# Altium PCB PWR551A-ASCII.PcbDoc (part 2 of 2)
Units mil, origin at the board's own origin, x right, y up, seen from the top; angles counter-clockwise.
Board outline 7100 x 3800 mil, 2 copper layers (Top Layer, Bottom Layer), stack 62 mil thick; 141 components, 57 nets, 323 pads, 168 vias.
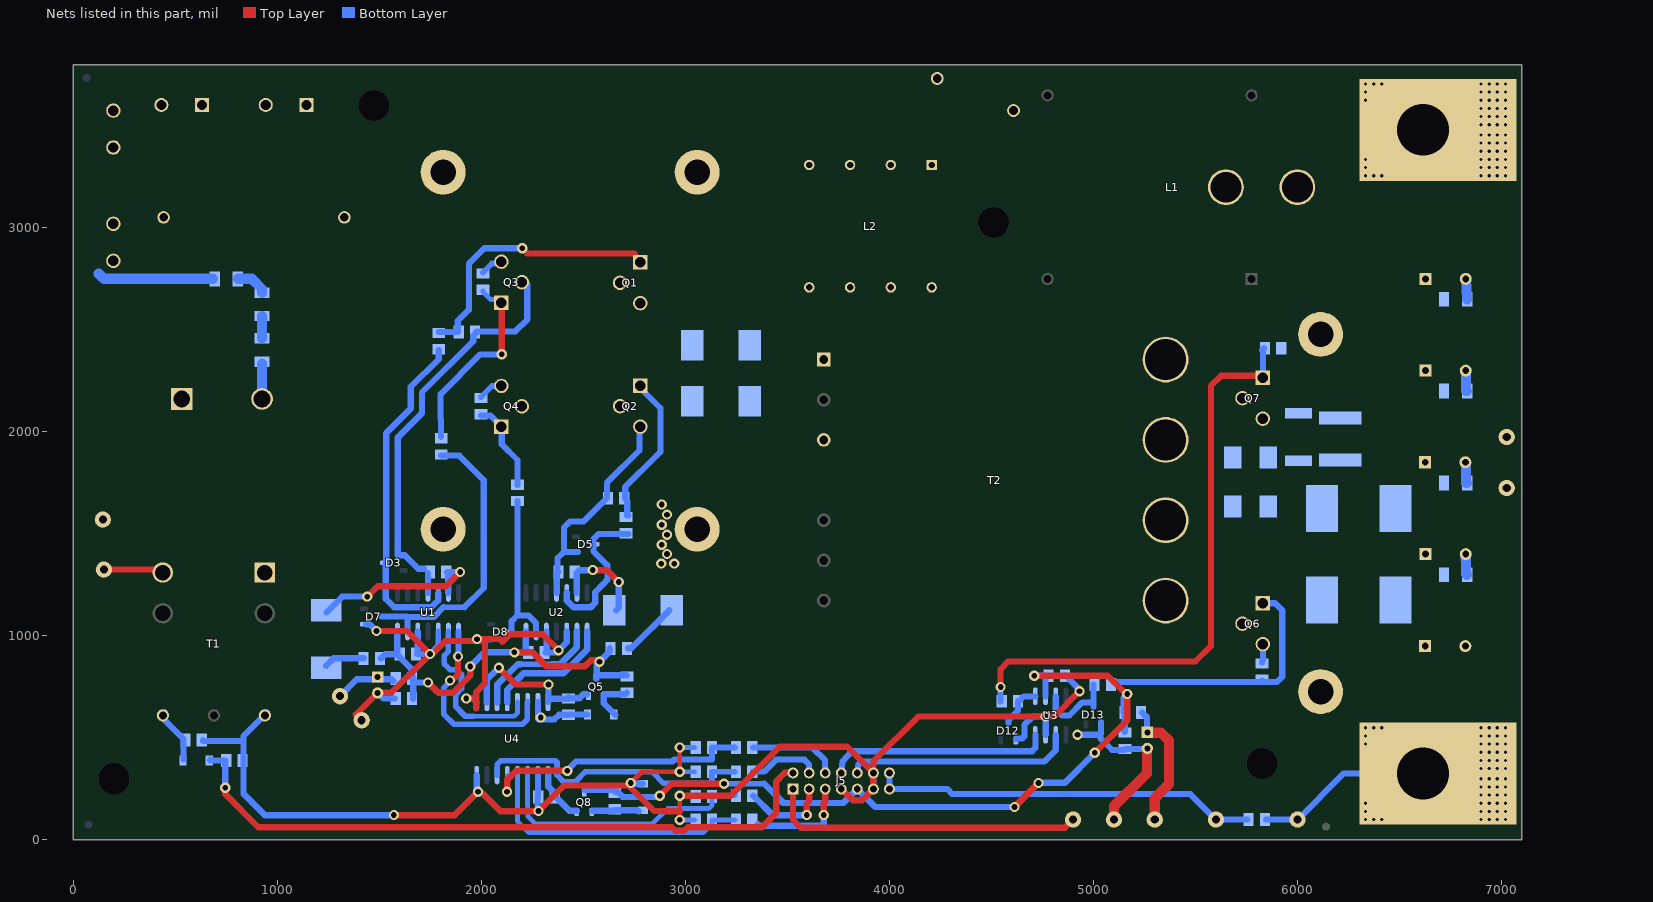
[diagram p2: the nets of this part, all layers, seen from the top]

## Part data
C1: "CAP, CERM, 0.22uF, 100V, +/-5%, C0G/NP0, 2220"
C2: "CAP, Film, 0.47uF, 275V, +/-20%, TH"
C3: "CAP, AL, 330uF, 450V, +/-20%, 0.553 ohm, TH"
C4 C5 C6 C7 C8: "CAP, AL, 1500uF, 16V, +/-20%, 0.031 ohm, TH"
C9 C10 C11 C12: library part C3216X7R1E105K/0.85, "CAP, CERM, 1 µF, 25 V, +/- 10%, X7R, 1206"
C13: "CAP, CERM, 1000pF, 400V, +/-20%, Y5U, Disc, 9.3x12.5mm"
C14 C15: "CAP, CERM, 0.1uF, 50V, +/-10%, X7R, 0805"
C16 C17 C18 C19 C20 C22 C23: "CAP, CERM, 1uF, 25V, +/-10%, X7R, 0805"
C21 C24: "CAP, AL, 22uF, 35V, +/-20%, TH"
D1: "Diode, Ultrafast, 100V, 0.15A, SOD-123"
D2 D9 D10 D11: "Diode, Ultrafast, 600 V, 3 A, SMC"
D3 D5 D7 D8 D12 D13: library part bat54-7-F, "Diode, Schottky, 30V, 0.2A, SOT-23"
D4 D6: "Diode, Superfast Rectifier, 100V, 3A, SMB"
D14 D15: "Diode, Zener, 5.6V, 500mW, SOD-123"
FC1 FC2: "Fuse Holder, 10A, TH"
FID1 FID2 FID3: "Fiducial mark.  There is nothing to buy or mount."
H1 H2 H3 H4: "Standoff, Hex, 0.5\"L #6-32 Nylon"
H5 H6 H7 H8: "HEX STANDOFF 6-32 NYLON 1-3/4\""
H27 H28 H29 H30 H31 H32: "MACHINE SCREW PAN PHILLIPS M3 5mm"
HS1 HS2 HS3: "HEATSINK VERT MAX CLIP, BLACK, 2 INCHES"
J1 J2: library part ED120/2DS, "TERMINAL BLOCK 5.08MM VERT 2POS, TH"
J3 J4: "Terminal 70A Lug"
J5: "Receptacle, 7x2, 2mm, TH"
L1: "Inductor, Shielded, ?, 2uH, A, 0.0009 ohm, TH"
L2: "Inductor, Shielded, ?, 26uH, A, 0.027 ohm, TH"
Logo1: library part TI_Logo, "Texas Instrument Corporate Signature"
LOGO2 LOGO5 LOGO8: library part IEC_HighVoltage, "IEC 61010-1 High Voltage Warning"
LOGO3 LOGO4 LOGO6 LOGO7: library part IEC_HotSurface, "IEC 61010-1 Hot Surface Warning"
Logo9: library part Pb-Free
Q1 Q2 Q3 Q4: "MOSFET, N-CH, 650V, 20.7A, TO-220AB"
Q5 Q8: library part "MMBT2222A, Fairchild Semiconductor", "Transistor, NPN, 40V, 0.15A, SOT-23"
Q6 Q7: "MOSFET, N-CH, 80V, 100A, TO-220AB"
R1: "RES, 48.7 ohm, 1%, 0.125W, 0805"
R2: "RES, 4.87k ohm, 1%, 0.125W, 0805"
R3 R12 R14: "RES, 1.0Meg ohm, 5%, 0.25W, 1206"
R4 R5 R13 R15: "RES, 3.01 ohm, 1%, 0.125W, 0805"
R6: "RES, 100 k, 1%, 1 W, 2512"
R7 R8: "RES, 1.00k ohm, 1%, 2W, 4527"
R9: "RES, 49.9, 1%, 0.125 W, 0805"
R10 R11 R16 R17 R24 R25: "RES, 10.0k ohm, 1%, 0.125W, 0805"
R18 R19: "RES, 2.20 ohm, 1%, 0.125W, 0805"
R20 R26 R27 R30 R32 R34: "RES, 7.15k ohm, 1%, 0.125W, 0805"
R21 R22: "RES, 6.19 ohm, 1%, 0.125W, 0805"
R23 R29: "RES, 5.11 ohm, 1%, 0.125W, 0805"
R28 R31 R33 R35: "RES, 5.11k ohm, 1%, 0.125W, 0805"
T1: "Transformer, 20 mH, TH"
T2: "Transformer, 2.75mH, TH"
TP1 TP4 TP8 TP10: library part 5000, "Test Point, Miniature, Red, TH"
TP2 TP3 TP7: library part 5002, "Test Point, Miniature, White, TH"
TP5 TP6 TP9 TP11: library part 5001, "Test Point, Miniature, Black, TH"
U1 U2: "High-Speed,4A, 600V High-side Low-side Gate Driver Device, D0014A"
U3: "Dual 5-A High-Speed Low-Side Gate Driver, D0008A"
U4: "150 Mbps Quad Channels, 4 / 0, Digital Isolator, 3.3 V / 5 V, -40 to +125 degC, 16-pin SOIC (DW), Green (RoHS & no Sb/Br)"
ZZ1 ZZ2 ZZ3 ZZ4: library part AssemblyNote

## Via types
v1: diameter 32, hole 16, Top Layer to Bottom Layer, 116 vias
v2: diameter 50, hole 28, Top Layer to Bottom Layer, tented both sides, 52 vias

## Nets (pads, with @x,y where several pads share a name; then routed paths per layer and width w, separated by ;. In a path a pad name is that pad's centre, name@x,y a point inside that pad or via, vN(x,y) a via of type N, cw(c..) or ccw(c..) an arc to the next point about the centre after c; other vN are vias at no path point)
CS: D1.1 J5.2 R1.1 | length 3309.7
  Top Layer w31.5: v2(745,255.91) 745,225 907.01,62.99 2933.28,62.99 2950.59,45.68 2994.29,45.68 3011.6,62.99 3375.71,62.99 3444.88,132.17 3444.88,286.44 3487.14,328.7 J5.2@3527.8,328.7
  Bottom Layer w30: D1.1@670,395 670,390 745,390 v2(745,255.91)
GND: C1.1 C4.2 C5.2 C6.2 C7.2 C8.2 C9.1 C10.1 C11.1 C12.1 C13.1 C18.1 C22.1 C23.1 C24.2 D12.1 D13.1 D15.2 HS3.1 HS3.2 J4.1 J5.7 J5.11 J5.12 Q6.3 Q7.3 R1.2 R2.2 R6.2 R24.2 R25.2 R28.1 R31.1 R33.1 R35.1 T1.3 TP5.1 TP11.1 U3.3 U4.2 U4.8 | length 8599.4
  Top Layer w23.62: v2@2720.47,267.72 v2(2732.28,279.53) 2787.4,334.65 v2(2972.48,334.65) 2972.48,452.71 v2(2972.44,452.76) ; 2832.68,155.51 2846.46,141.73 ; v2(2972.44,98.43) 2972.44,141.73 v2(2972.44,216.54)
  Top Layer w30: v2(2279.92,141.73) 2405.91,267.72 2720.47,267.72 2832.68,155.51 ; 2846.46,141.73 2890.16,141.73 ; J5.12@3921.3,328.7 3921.3,385.47 4140.83,605 v2(4765,605) 4807.76,605 v2(4931.1,728.35)
  Top Layer w31.5: v2(1571.26,122.05) 1869.29,122.05 v2(1983.46,236.22) ; v2@2004.33,230.32 2092.91,141.73 v2(2279.92,141.73) ; 2890.16,141.73 2972.44,141.73 ; v2(2972.44,216.54) 3222.09,216.54 3462.24,456.69 3793.31,456.69 3921.3,328.7 3921.3,250 3866.05,194.75 3819.72,194.75 3764.47,250 J5.7@3763.9,250
  Top Layer w50: TP11.1@5100,100 5100,165 5262.2,327.2 C24.2@5262.2,445.59
  Bottom Layer w23.62: v2@2972.44,106.3 2980.31,98.43 R31.1@3045.55,98.43 ; v2(2972.44,216.54) R28.1@3045.55,216.54 ; v2(2972.44,452.76) R33.1@3045.55,452.76 ; v2(2972.48,334.65) R35.1@3045.55,334.65
  Bottom Layer w30: R2.2@635,490 635,485 835,485 ; 835,225 835,485 ; T1.3@950,625 835,510 835,485 ; v2@2274.29,156.93 2274.29,210.63 2276.97,213.31 U4.2@2276.97,316.93 ; D12.1@4620.08,498.03 D12.1@4628.03,498.03 ; D12.1@4622.5,492.5 D12.1@4628.03,498.03 ; v2(4765,605) 4701.85,605 4661.42,564.57 4661.42,507.87 4651.57,498.03 D12.1@4628.03,498.03 ; C18.1@4865,805 4931.1,738.9 v2(4931.1,728.35) ; v2@4920.51,515 v2(4921.26,515.75) 5033.96,515.75 ; D13.1@5037.4,576.77 5037.4,519.19 5033.96,515.75 ; C24.2@5262.2,445.59 5158.31,445.59 5153.94,441.22 5090.67,441.22 5033.96,497.93 5033.96,515.75 ; R25.2@5825,870 5825,875 5830,880 Q6.3@5830,960
  Bottom Layer w31.5: 835,225 937.95,122.05 v2(1571.26,122.05) ; U4.8@1976.97,316.93 1976.97,242.72 v2(1983.46,236.22) ; v2@2738.09,275.1 D15.2@2791.73,275.1 ; J5.11@3920.73,250 3921.3,250 J5.12@3921.3,328.7 ; U3.3@4765,515 v2(4765,605)
  Bottom Layer w50: C6.2@6824,1850 6825,1850 6825,1750 C9.1@6830,1750 ; C5.2@6824,2300 6825,2300 6825,2200 C12.1@6830,2200 ; C4.2@6824,2750 6825,2750 C11.1@6830,2650 ; C10.1@6830,1300 6825,1305 C7.2@6825,1375 ; C7.2@6825,1375 6824,1376 6824,1400 6825,1400 C7.2@6825,1375
  other v1: 6332.91,3255.32 6372.91,3255.32 6412.91,3255.32 6899.17,3255.32 6939.17,3255.32 6979.17,3255.32 7019.17,3255.32 6332.91,3295.32 6899.17,3295.32 6939.17,3295.32 6979.17,3295.32 7019.17,3295.32 6332.91,3335.32 6899.17,3335.32 6939.17,3335.32 6979.17,3335.32 7019.17,3335.32 6899.17,3375.32 6939.17,3375.32 6979.17,3375.32 7019.17,3375.32 6899.17,3415.32 6939.17,3415.32 6979.17,3415.32 7019.17,3415.32 6899.17,3455.32 6939.17,3455.32 6979.17,3455.32 7019.17,3455.32 6899.17,3505.32 6939.17,3505.32 6979.17,3505.32 7019.17,3505.32 6899.17,3545.32 6939.17,3545.32 6979.17,3545.32 7019.17,3545.32 6899.17,3585.32 6939.17,3585.32 6979.17,3585.32 7019.17,3585.32 6332.91,3625.32 6899.17,3625.32 6939.17,3625.32 6979.17,3625.32 7019.17,3625.32 6332.91,3665.32 6899.17,3665.32 6939.17,3665.32 6979.17,3665.32 7019.17,3665.32 6332.91,3705.32 6372.91,3705.32 6412.91,3705.32 6899.17,3705.32 6939.17,3705.32 6979.17,3705.32 7019.17,3705.32
NetC1_2: C1.2 D4.1 D6.1 R6.1 R7.2 R8.2
NetC2_2: C2.2 C3.1 FC2.1 FC2.2 R3.2 T1.2 TP1.1 | length 870.4
  Top Layer w30: TP1.1@150,1325 T1.2@450,1325
  Bottom Layer w50: 125,2775 150,2750 R3.2@685.04,2750
NetC4_1: C4.1 C5.1 C6.1 C7.1 C8.1 C9.2 C10.2 C11.2 C12.2 J3.1 L1.14 R7.1 R8.1 R9.2 TP3.1 TP4.1 | length 898.2
  Bottom Layer w30: R9.2@5845,100 TP3.1@6000,100 6225,325 J3.1@6650,325
  other v1: 6332.91,100 6372.91,100 6412.91,100 6899.17,100 6939.17,100 6979.17,100 7019.17,100 6332.91,140 6899.17,140 6939.17,140 6979.17,140 7019.17,140 6332.91,180 6899.17,180 6939.17,180 6979.17,180 7019.17,180 6899.17,220 6939.17,220 6979.17,220 7019.17,220 6899.17,260 6939.17,260 6979.17,260 7019.17,260 6899.17,300 6939.17,300 6979.17,300 7019.17,300 6899.17,350 6939.17,350 6979.17,350 7019.17,350 6899.17,390 6939.17,390 6979.17,390 7019.17,390 6899.17,430 6939.17,430 6979.17,430 7019.17,430 6332.91,470 6899.17,470 6939.17,470 6979.17,470 7019.17,470 6332.91,510 6899.17,510 6939.17,510 6979.17,510 7019.17,510 6332.91,550 6372.91,550 6412.91,550 6899.17,550 6939.17,550 6979.17,550 7019.17,550
NetC14_1: C14.1 D3.1 L2.1 L2.2 L2.3 L2.4 Q1.3 Q3.2 R11.2 U1.11 | length 1982.9
  Bottom Layer w30: 1708.66,2090.55 1708.66,2192.91 1960,2444.25 1960,2471.81 1974.13,2485.94 1974.13,2490.16 1976.2,2492.22 2167.22,2492.22 2225,2550 2225,2725 Q3.2@2200,2725 ; U1.11@1738.58,1210.63 C14.1@1738.58,1308.78
  Bottom Layer w31.5: D3.1@1608.27,1395.67 1624.02,1395.67 1690.94,1328.74 1718.62,1328.74 ; D3.1@1608.27,1395.77 1590.55,1395.77 1590.55,1972.44 1708.66,2090.55
NetC14_2: C14.2 D10.1 U1.13 | length 916.8
  Top Layer w31.5: v2@1433.46,1185.04 v2(1440.94,1192.52) 1492.52,1244.09 1827.17,1244.09 v2(1896.06,1312.99)
  Bottom Layer w30: D10.1@1240.16,1114.25 1318.43,1192.52 v2(1440.94,1192.52)
  Bottom Layer w31.5: U1.13@1838.58,1210.63 1838.58,1307.2 1832.8,1312.99 v2(1896.06,1312.99)
NetC15_1: C15.1 D5.1 Q2.3 Q4.2 R10.1 T2.3 U2.11 | length 1092.1
  Bottom Layer w30: C15.1@2377.72,1312.99 2374.02,1316.69 2374.02,1381.89 2405.51,1413.39 ; D5.1@2474.41,1411.42 2407.48,1411.42 2405.51,1413.39 ; Q2.3@2775,2025 2775,1910 2615,1750 2615,1675 2500,1560 2434.02,1560 2405.51,1531.5 2405.51,1413.39
  Bottom Layer w31.5: U2.11@2368.5,1210.63 2368.5,1308.78 C15.1@2372.72,1312.99
NetC15_2: C15.2 D11.1 U2.13 | length 472.3
  Top Layer w31.5: v2(2545.67,1322.83) 2614.57,1322.83 2663.78,1273.62 v2@2663.78,1263.78
  Bottom Layer w31.5: U2.13@2468.5,1210.63 2468.5,1308.94 2472.56,1312.99 2482.4,1322.83 v2(2545.67,1322.83) ; D11.1@2661.73,1125.98 2673.62,1137.87 v2(2673.62,1263.78)
NetC19_2: C19.2 Q5.2 U4.10 U4.16 | length 739.2
  Top Layer w31.5: v2(2085.86,843.81) 2167.85,761.81 v2(2329.13,761.81)
  Bottom Layer w31.5: U4.10@2026.97,675.2 2026.97,784.92 v2(2085.86,843.81) ; U4.16@2329.13,678.27 v2(2329.13,761.81) ; 2342.05,691.18 2425.2,691.18 C19.2@2427.56,693.54 ; C19.2@2427.56,698.54 2432.56,693.54 2478.98,693.54 2500,714.57 Q5.2@2515.75,714.57
NetC21_1: C21.1 R23.2 TP8.1 | length 298.9
  Bottom Layer w31.5: TP8.1@1307.09,704.72 1389.76,787.4 1559.72,787.4 R23.2@1568.2,778.93
NetC22_2: C22.2 Q8.2 U4.1 | length 259.2
  Bottom Layer w31.5: U4.1@2326.97,316.93 2326.97,263.31 2359.29,230.99 C22.2@2359.29,215.63 ; C22.2@2359.29,210.63 C22.2@2359.29,215.63 ; Q8.2@2468.8,143.13 2431.79,143.13 C22.2@2359.29,215.63
NetC24_1: C24.1 R29.2 TP10.1 | length 648.3
  Top Layer w50: C24.1@5262.2,525.59 5331.1,525.59 5370.47,486.22 5370.47,275.47 5300,205 TP10.1@5300,100
  Bottom Layer w31.5: R29.2@5238.31,624.02 5262.2,600.12 C24.1@5262.2,525.59
NetD1_2: D1.2 R2.1 T1.5 | length 447.3
  Bottom Layer w30: T1.5@450,625 450,585 540,495 D1.2@540,395 ; D1.2@540,395 540,485 D1.2@540,395
NetD2_1: D2.1 Q1.2 Q2.2 T1.1
NetD2_2: D2.2 D9.1 L2.5 L2.6 L2.7 L2.8 T2.1
NetD3_3: D3.3 R4.1 U1.12 | length 1650.7
  Bottom Layer w30: D3.3@1533.46,1358.27 1531.5,1356.3 1531.5,1181.33 1572.51,1140.32 1754.66,1140.32 1788.58,1174.25 U1.12@1788.58,1210.63 ; 1655,2220.47 1791.34,2356.81 R4.1@1791.34,2399.88
  Bottom Layer w31.5: D3.3@1533.46,1358.27 1533.46,1994.09 1655,2115.63 1655,2220.47
NetD4_2: D4.2 Q7.2 T2.10
NetD5_3: D5.3 R5.1 U2.12 | length 745.9
  Bottom Layer w30: D5.3@2549.21,1448.82 2549.21,1415.75 2618.11,1346.85 2618.11,1274.61 2597.48,1253.98 ; D5.3@2550,1449.61 2550,1475.2 2574.8,1500 R5.1@2720,1500
  Bottom Layer w31.5: U2.12@2418.5,1210.63 2418.5,1173.19 2452.12,1139.57 2534.89,1139.57 2558.06,1162.75 2558.06,1214.57 2597.48,1253.98
NetD6_2: D6.2 Q6.2 T2.9
NetD7_3: D7.3 R15.1 U1.6 | length 1421.7
  Bottom Layer w27.56: 1814.06,1140.32 1917.32,1140.32
  Bottom Layer w30: D7.3@1509.84,1094.49 1631.89,1094.49 1634.42,1091.96 ; U1.6@1638.58,1021.65 1638.58,1087.8 1634.42,1091.96 ; R15.1@1803.15,1884.13 1891.46,1884.13 2011.81,1763.78 2011.81,1234.81 1917.32,1140.32 ; 1814.06,1140.32 1765.69,1091.96 1634.42,1091.96
NetD8_3: D8.3 R13.1 U2.6 | length 801
  Bottom Layer w30: D8.3@2148.43,1019.68 2148.43,1071.85 2177.17,1100.59 ; R13.1@2177.17,1660.79 2177.17,1100.59 ; U2.6@2268.5,1021.65 2268.5,1062.6 2230.51,1100.59 2177.17,1100.59
NetD10_2: D10.2 R18.2 | length 197.5
  Bottom Layer w31.5: D10.2@1240.16,854.25 1275.67,889.76 R18.2@1422.99,889.76
NetD11_2: D11.2 R19.2 | length 280.6
  Bottom Layer w31.5: R19.2@2718.62,938.98 2734.72,938.98 D11.2@2921.73,1125.98
NetD12_3: D12.3 R21.1 U3.5 | length 216.6
  Bottom Layer w30: D12.3@4582.68,572.83 4582.68,586.61 4629.91,633.84 R21.1@4629.91,679.9 ; R21.1@4635,680 4659,704 U3.5@4715,704
NetD13_3: D13.3 R22.1 U3.7 | length 392.5
  Bottom Layer w30: U3.7@4815,704 4815,640 4845,610 4881.89,610 4945.91,674.02 5000,674.02 D13.3@5000,651.57 ; D13.3@5000.67,679.65 R22.1@5000.67,761.81
NetD14_1: D14.1 Q5.1 R20.2 | length 239
  Bottom Layer w31.5: D14.1@2656.04,614.17 2600.39,669.82 2600.39,714.57 2705.75,714.57 R20.2@2712.99,721.81
NetD15_1: D15.1 Q8.1 R26.2 | length 232
  Bottom Layer w31.5: Q8.1@2543.8,143.13 2651.12,143.13 2653.94,145.94 2765.73,145.94 D15.1@2772.05,139.63
NetFC1_1: FC1.1 FC1.2 J1.1 J1.2
NetL1_13: L1.13 T2.7 T2.12
NetQ1_1: Q1.1 R4.2 R11.1 | length 1358.7
  Top Layer w30: v2(2200,2900) 2225,2875 2750,2875 Q1.1@2775,2825
  Bottom Layer w30: R4.2@1791.34,2489.88 1791.61,2490.16 1884.13,2490.16 1884.13,2543.58 1938.98,2598.43 1938.98,2824.8 2014.17,2900 v2(2200,2900)
NetQ2_1: Q2.1 R5.2 R10.2 | length 767.1
  Bottom Layer w30: R5.2@2720,1590 2715,1590 2715,1660 2705,1675 2705,1730 2859.25,1884.25 2860.63,1884.25 2877.95,1901.57 2877.95,2115.75 Q2.1@2767.72,2225.98 ; Q2.1@2770,2225 Q2.1@2775,2225
NetQ3_1: Q3.1 R15.2 R17.1 | length 927.1
  Top Layer w30: v2(2100,2380) Q3.1@2100,2625
  Bottom Layer w23.62: R17.1@2007.87,2691.22 2007.87,2687.01 2046.65,2648.23 Q3.1@2076.77,2648.23
  Bottom Layer w30: R15.2@1803.15,1974.13 1803.15,2061.85 1800,2065 1800,2185 1995,2380 v2(2100,2380)
NetQ4_1: Q4.1 R13.2 R16.1 | length 441.3
  Bottom Layer w30: R16.1@1998.03,2080.98 2044.02,2080.98 2100,2025 2100,1939.37 2177.17,1862.2 R13.2@2177.17,1740.79
NetQ6_1: Q6.1 R22.2 R25.1 | length 1274.9
  Bottom Layer w30: R22.2@5100,775 R25.1@5825,775 ; R25.1@5825,780 R25.1@5825,775 ; Q6.1@5830,1160 5890,1160 5925,1125 5925,800 5900,775 R25.1@5825,775
NetQ7_1: Q7.1 R21.2 R24.1 | length 2941.7
  Top Layer w30: v2(4545,750) 4545,836.62 4583.38,875 5500,875 5575,950 5575,2225 5625,2275 5825,2275 Q7.1@5830,2265
  Bottom Layer w30: R21.2@4545,680 v2(4545,750) ; Q7.1@5830,2265 5830,2395 5825,2400 R24.1@5835,2410
NetR3_1: R3.1 R12.2 | length 156.5
  Bottom Layer w50: R3.1@807.09,2750 875,2750 925,2700 R12.2@925,2682.09
NetR12_1: R12.1 R14.2 | length 109.3
  Bottom Layer w50: R14.2@925,2458.66 R12.1@925,2567.91
NetR27_2: R27.2 R28.2 U4.3 | length 1318.9
  Bottom Layer w23.62: U4.3@2226.97,316.93 2225.67,315.63 2225.67,169.55 2226.97,168.25 2226.97,115.55 2263.78,78.74 2838.58,78.74 2913.39,153.54 3015.5,153.54 3015.69,153.74 3114.37,153.74 3130.55,169.92 R28.2@3130.55,213.13 ; R28.2@3130.55,216.54 R28.2@3130.55,213.13 ; R27.2@3242.4,216.54 3133.96,216.54 R28.2@3130.55,213.13
NetR30_2: R30.2 R31.2 U4.4 | length 1346.6
  Bottom Layer w23.62: U4.4@2176.97,316.93 2176.97,92.24 2232.72,36.5 3087.68,36.5 3130.55,79.37 R31.2@3130.55,98.43 ; R31.2@3133.96,98.43 R30.2@3242.4,98.43
NetR32_2: R32.2 R33.2 U4.5 | length 1360.9
  Top Layer w31.5: v2(2125.98,236.22) 2125.98,294.29 2170.27,338.58 v2(2421.26,338.58)
  Bottom Layer w23.62: v2(2125.98,236.22) 2126.97,237.2 U4.5@2126.97,316.93
  Bottom Layer w30: v2(2421.26,338.58) 2431.26,338.58 2431.26,351.72 2463.39,383.86 2935.43,383.86 2946.02,394.44 3014.18,394.44 3014.37,394.26 3086.73,394.26 3086.92,394.44 3130.55,394.44 R33.2@3130.55,452.76 ; R33.2@3134.51,448.8 3138.47,452.76 R32.2@3242.4,452.76
NetR34_2: R34.2 R35.2 U4.6 | length 1398.8
  Bottom Layer w27.56: U4.6@2077,317.87 2077,370.21 2095.71,388.92 2363.05,388.92 2370.48,381.49 2370.48,317.55 2402.46,285.56 2460.76,285.56 2510.11,334.91 2835.79,334.91 2893.15,277.56 3014.68,277.56 3014.87,277.37 3086.23,277.37 3086.42,277.56 3124.01,277.56 3130.55,284.09 R35.2@3130.55,334.65 ; R35.2@3133.65,331.55 R35.2@3136.74,334.65 ; R35.2@3139.53,334.65 R34.2@3242.4,334.65
NetU1_1: U1.1 U4.14 | length 965.9
  Top Layer w30: v2(1846.85,781.5) 1856.69,781.5 1886.22,811.02 v2(1886.22,899.61)
  Bottom Layer w27.56: v2(1846.85,781.5) 1846.85,775.98 1814.96,744.09 1814.96,618.11 1866.14,566.93 2200.79,566.93 2224.81,590.95 2224.81,673.94 U4.14@2227,676.13
  Bottom Layer w30: v2@1888.58,899.61 U1.1@1888.58,1021.65
NetU1_2: U1.2 U4.13 | length 824.8
  Bottom Layer w23.62: 1960.02,606.49 2161.61,606.49 2177,621.88 U4.13@2177,676.13
  Bottom Layer w27.56: U1.2@1838.58,1021.65 1838.58,923.78 1818.9,904.1 1818.9,862.2 1846.46,834.65 1879.37,834.65 1902.99,811.02 1902.99,742.13 1874.81,713.95 1874.81,671.69 1875,671.5 1875,652.64 1921.15,606.49 1960.02,606.49
NetU2_1: U2.1 U4.12 | length 623
  Bottom Layer w31.5: U4.12@2126.97,675.2 2126.97,736.81 2188.98,798.82 2189.17,798.82 2208.2,817.86 2365.63,817.86 2365.82,818.05 2403.37,818.05 2518.5,933.18 U2.1@2518.5,1021.65
NetU2_2: U2.2 U4.11 | length 644.7
  Bottom Layer w27.56: 2178.19,861.54 2347.8,861.54
  Bottom Layer w31.5: U4.11@2076.97,675.2 2076.97,760.32 2178.19,861.54 2178.38,861.35 2192.54,861.35 ; 2347.62,861.35 2347.8,861.54 2385.35,861.54 2468.5,944.69 U2.2@2468.5,1021.65
OUTA: J5.3 R27.1 | length 434.2
  Top Layer w31.5: v2(3594.49,122.05) 3594.49,178.93 3606.5,190.94 J5.3@3606.5,250
  Bottom Layer w31.5: R27.1@3332.4,216.54 3426.89,122.05 v2(3594.49,122.05)
OUTB: J5.5 R30.1 | length 507.3
  Top Layer w31.5: v2(3677.56,122.05) 3677.56,182.2 3685.2,189.84 J5.5@3685.2,250
  Bottom Layer w31.5: 3354.25,76.57 3361.34,69.49 3572.45,69.49 3572.64,69.3 3671.66,69.3 3677.56,75.2 v2(3677.56,122.05) ; J5.5@3684.63,250 J5.5@3685.2,250
OUTC: J5.6 R32.1 | length 439.9
  Bottom Layer w30: R32.1@3332.4,452.76 3622.24,452.76 3685,390 J5.6@3685.2,328.7
OUTD: J5.4 R34.1 | length 360.7
  Top Layer w30: J5.4@3606.5,328.7 3605,325 J5.4@3610,330
  Bottom Layer w30: R34.1@3332.4,334.65 3385.83,334.65 3444.88,393.7 3582.68,393.7 3606.5,369.88 J5.4@3606.5,328.7
OUTE: J5.10 U3.2 | length 1112.9
  Bottom Layer w30: J5.10@3842.6,328.7 3843.9,330 3845,365 3865,385 4075,385 4760,385 4815,440 U3.2@4815,515
OUTF: J5.8 U3.4 | length 1095.6
  Bottom Layer w30: J5.8@3763.9,328.7 3770,385 3815,435 4700,435 4700,436.25 4715,451.25 U3.4@4715,515.51
PWRGND: C2.1 C3.2 C13.2 C16.1 C17.1 C19.1 C20.1 C21.2 D7.1 D8.1 D9.2 D14.2 HS1.1 HS1.2 HS2.1 HS2.2 J2.1 J2.2 Q3.3 Q4.3 R14.1 R16.2 R17.2 TP6.1 TP9.1 U1.3 U1.5 U2.3 U2.5 U4.9 U4.15 | length 3562.9
  Top Layer w30: 1384.25,614.17 1385.51,614.17 1492.52,721.18 1558.74,721.18 v2(1748.43,910.87) ; v2(1486.22,1023.62) 1635.67,1023.62 v2(1748.43,910.87) ; v2(1925.59,692.91) 1974.8,692.91 ; 1974.8,643.7 1974.8,692.91 ; v2(1978.35,984.25) 2090.55,984.25 2098.43,976.38 ; 2104.53,970.28 2142.13,1007.87 2299.61,1007.87 v2(2378.35,929.13) ; v2(1748.43,910.87) 1756.85,910.87 1758.27,909.45 1823.23,974.41 2017.72,974.41 2017.72,767.72 1974.8,724.8 1974.8,692.91
  Bottom Layer w27.56: 1788.58,951.02 U1.3@1788.58,1021.65 ; R16.2@1998.03,2170.98 2052.05,2225 Q4.3@2100,2225 ; R17.2@2007.87,2781.22 2051.65,2825 Q3.3@2100,2825
  Bottom Layer w30: D7.1@1435.04,1057.09 1452.76,1057.09 v2(1486.22,1023.62) ; C21.2@1492.52,721.18 1520.79,692.91 C20.1@1575.47,692.91 ; C16.1@1685.16,910.87 C16.1@1688.58,910.87 ; U1.5@1688.58,1021.65 C16.1@1688.58,910.87 ; 1788.58,951.02 v2(1748.43,910.87) C16.1@1688.58,910.87 ; v2(1925.59,692.91) 1959.25,692.91 U4.9@1976.97,675.2 ; v2(1978.35,984.25) 1980.41,982.18 D8.1@2045.93,982.18 ; v2@2276.97,614.17 U4.15@2276.97,641.73 ; U4.15@2277,676.13 2277,593.08 2279.53,590.55 2358.27,590.55 2381.26,613.54 C19.1@2427.56,613.54 ; U2.5@2318.5,1021.65 2318.5,922.72 2315.08,919.29 2368.5,919.29 v2(2378.35,929.13) 2418.5,969.29 U2.3@2418.5,1021.65 ; C19.1@2427.56,614.17 D14.2@2520.04,614.17
  Bottom Layer w50: C3.2@925,2175 R14.1@925,2334.65
  other v2: 2291.34,599.87 2881.89,1354.33 2944.88,1354.33 2909.45,1401.57 2883.86,1446.85 2909.45,1496.06 2883.86,1545.28 2909.45,1594.49 2883.86,1643.7
SYNC: J5.1 TP7.1 | length 1557.2
  Top Layer w30: 3527.12,114.05 3527.12,98.43 3565.55,60 4860,60 TP7.1@4900,100 ; 3527.13,114.06 3527.13,143.59 3527.8,144.25 J5.1@3527.8,250
VBIAS: C18.2 C23.2 J5.9 Q8.3 R26.1 R29.1 U3.6 | length 3959.6
  Top Layer w30: v2(4710,805) 5070,805 5150,725 v2(5165,715)
  Top Layer w31.5: v2(2874.02,216.54) 2933.07,275.59 v2(3188.97,275.59) ; v2(4612.6,161.42) v2(4730.71,279.53) ; v2(5006.3,427.17) 5165,585.87 v2(5165,715)
  Bottom Layer w20: C18.2@4765,805 C18.2@4775,805
  Bottom Layer w27.56: v2(3188.97,275.59) 3385.83,275.59
  Bottom Layer w30: v2(4710,805) 4765,805 U3.6@4765,704
  Bottom Layer w31.5: Q8.3@2506.3,245.63 2644.25,245.63 2653.94,235.94 2667.99,235.94 2693.31,210.63 2868.11,210.63 v2(2874.02,216.54) ; 3385.83,275.59 3480.31,181.1 3773.7,181.1 3842.6,250 3931.18,161.42 v2(4612.6,161.42) ; v2(4730.71,279.53) 4858.66,279.53 v2(5006.3,427.17) ; C23.2@5153.94,531.22 5153.94,618.39 5148.31,624.02 5148.31,698.31 v2(5165,715)
VBIAS2: C16.2 C17.2 C20.2 Q5.3 R18.1 R19.1 R20.1 R23.1 U1.7 U2.7 | length 2030.6
  Top Layer w31.5: v2(1738.58,771.65) 1787.8,722.44 1862.39,722.44 1945.28,805.32 v2(1945.28,850.39) ; v2(2161.81,919.29) 2250.39,919.29 2319.29,850.39 2506.3,850.39 2535.83,879.92 2585.04,879.92 v2(2578.74,873.62)
  Bottom Layer w31.5: R18.1@1507.99,889.76 1529.09,910.87 C16.2@1588.58,910.87 ; U1.7@1588.58,1021.65 C16.2@1588.58,910.87 ; R23.1@1660.47,791.34 1660.47,835.08 1643.93,851.62 1643.66,851.62 1627.41,867.87 1627.41,868.14 1588.58,906.97 C16.2@1588.58,910.87 ; C20.2@1665.47,692.91 R23.1@1665.47,771.65 ; R23.1@1665.47,791.34 R23.1@1665.47,771.65 ; v2(1738.58,771.65) R23.1@1665.47,771.65 ; v2(1945.28,850.39) 2014.17,919.29 v2(2161.81,919.29) C17.2@2218.5,919.29 ; U2.7@2218.5,1021.65 C17.2@2218.5,919.29 ; C17.2@2225.08,919.29 C17.2@2218.5,919.29 ; Q5.3@2562.99,789.37 2562.99,809.45 2565.35,811.81 2565.35,860.24 2628.62,923.5 R19.1@2628.62,938.98 ; Q5.3@2570.35,806.81 R20.1@2712.99,806.81
VOUT: J5.13 J5.14 R9.1 TP2.1 | length 1895.8
  Bottom Layer w30: J5.14@4000,328.7 4000,250 4282.48,250 4307.48,225 5475,225 TP2.1@5600,100 R9.1@5755,100
pads on no net: D3.2 D5.2 D7.2 D8.2 D12.2 D13.2 FID1.1 FID2.1 FID3.1 H1.0 H2.0 H3.0 H4.0 H5.0 H5.MH H6.0 H6.MH H7.0 H7.MH H8.0 H8.MH H27.0 H28.0 H29.0 H30.0 H31.0 H32.0 L1.1 L1.6 L1.7 L1.12 T1.4 T1.6 T1.7 T2.2 T2.4 T2.5 T2.6 U1.4 U1.8 U1.9 U1.10 U1.14 U2.4 U2.8 U2.9 U2.10 U2.14 U3.1 U3.8 U4.7

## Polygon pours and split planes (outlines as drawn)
NetFC1_1 on Top Layer "Top Layer, Top-NET00016" (solid, pour order 35): 79.72,3662.4 80,3350 280,3350 405,3475 637.5,3475 681.69,3493.31 700,3537.5 700,3725 148.62,3725.39
GND on Top Layer "Top Layer, Top-GND 2" (solid, remove dead copper, pour order 46): 1502.36,33.46 6051.18,35.43 6122.05,118.11 6190.94,118.11 6210.63,137.8 6210.63,836.61 3840,835 3815,810 3525,810 3208.66,492.13 2952.76,492.13 2854.33,393.7 1732.28,393.7 1699.21,358.27 1502.36,161.42
PWRGND on Top Layer "Top Layer, Top-PWRGND" (solid, remove dead copper, pour order 34): 1785,2210 1792.32,2192.32 1810,2185 2110,2185 2127.68,2192.32 2135,2210 2135,2240 2127.68,2257.68 2110,2265 1985,2265 1975.52,2280.17 1960.33,2334.38 1964.98,2742.97 1966.44,2746.44 2010,2790 2115,2790 2129.14,2795.86 2135,2810 2135,2845 2129.14,2859.14 2115,2865 2060,2865 1885,2865 1835,2851.6 1798.4,2815 1785,2765
NetC14_1 on Top Layer "Top Layer, Top-NET00025" (solid, remove dead copper, pour order 37): 2550,2400 3050,2400 3050,2675 2800,2675 2750,2625 2600,2625 2450,2775 2275,2775 2200,2775 2182.32,2767.68 2175,2750 2175,2700 2182.32,2682.32 2200,2675 2275,2675
NetD2_2 on Top Layer "Top Layer, Top-NET00003" (solid, pour order 38): 3525,2350 3532.32,2332.32 3550,2325 3914.64,2325 3932.32,2332.32 4242.68,2642.68 4250,2660.36 4250,2725 4242.68,2742.68 4225,2750 3550,2750 3532.32,2742.68 3525,2725
NetL1_13 on Top Layer "Top Layer, Top-NET00002" (solid, pour order 40): 4725,2525 4725,1050 4750,1050 5325,1050 5360.36,1064.64 5375,1100 5375,1200 5358.25,1262.5 5312.5,1308.25 5250,1325 5150,1325 5050,1425 5050,2125 5150,2225 5350,2225 5412.5,2241.75 5458.25,2287.5 5475,2350 5475,2525 5475,2750 5750,3025 5750,3300 5225,3300 5225,3025
GND on Top Layer "Top Layer, Top-GND 1" (solid, pour order 41): 6150,3775 6025,3610 6175,3450 6175,3275 6335,3115 6335,2695 5700,2695 5700,600 6215,600 6215,685 7080,685 7075,3775
NetC15_1 on Top Layer "Top Layer, Top-NET00007" (solid, remove dead copper, pour order 42): 2550,1800 3775,1800 3775,2075 2775,2075 2725,2025 2600,2025 2450,2175 2275,2175 2200,2175 2182.32,2167.68 2175,2150 2175,2100 2182.32,2082.32 2200,2075 2275,2075
PWRGND on Top Layer "Top Layer, Top-PWRGND 3" (solid, pour order 44): 1850,3725 1850,3050 1863.4,3000 1900,2963.4 1950,2950 2025,3025 2938.37,3025 2976.8,3032.68 3009.33,3054.54 3675,3725
NetC14_1 on Top Layer "Top Layer, Top-NET00025 1" (solid, pour order 47): 3565.36,3375 3547.68,3367.68 3087.32,2907.32 3069.64,2900 3010.36,2900 2992.68,2892.68 2732.32,2632.32 2725,2614.64 2725,2450 2732.32,2432.32 2750,2425 3259.93,2425 3277.27,2431.99 3392.34,2542.63 3400,2560.64 3400,2714.64 3407.32,2732.32 3642.68,2967.68 3660.36,2975 4225,2975 4242.68,2982.32 4250,3000 4250,3350 4242.68,3367.68 4225,3375
PWRGND on Top Layer "Top Layer, Top-PWRGND 1" (solid, pour order 39): 50,1575 63.4,1525 100,1488.4 150,1475 1033.58,1475 1071.85,1467.39 1104.29,1445.71 1167.72,1381.89 1866.54,1381.89 1925.59,1391.73 1974.8,1440.94 1965.39,3625.35 1951.88,3675.2 1915.29,3711.66 1865.4,3725 925,3725 875,3711.6 838.4,3675 825,3625 825,3441.42 817.39,3403.15 795.71,3370.71 529.29,3104.29 507.61,3071.85 500,3033.58 500,2741.42 492.39,2703.15 470.71,2670.71 429.29,2629.29 396.85,2607.61 358.58,2600 150,2600 100,2586.6 63.4,2550 50,2500
PWRGND on Top Layer "Top Layer, Top-PWRGND 4" (solid, pour order 45): 1600,1925 1550,1911.6 1513.4,1875 1500,1825 1502.36,1411.42 1512.2,1391.73 1531.89,1381.89 2781.89,1381.89 3018.11,1214.57 3400,1213.4 3436.6,1250 3450,1300 3450,1575 3436.6,1625 3400,1661.6 3350,1675 2491.42,1675 2453.15,1682.61 2420.71,1704.29 2229.29,1895.71 2196.85,1917.39 2158.58,1925
PWRGND on Top Layer "Top Layer, Top-No Net" (solid, pour order 48): 1148.03,1204.72 1285.83,1342.52 2762.2,1342.52 2860.63,1244.09 2939.37,1244.09 2998.43,1185.04 2998.43,1066.93 2762.2,830.71 2763.78,653.54 2664.57,559.06 1383.15,559.06 1344.88,594.49 1344.88,791.34 1338.58,797.24 1161.42,797.24 1151.57,816.93
PWRGND on Top Layer "Top Layer, Top-PWRGND 2" (solid, pour order 43): 3425.2,3551.18 3956.69,3551.18 4275.59,3712.6 4275.59,3775.66 3025,3775 2675,3425 2675,3250 3125,3250
GND on Top Layer "Top Layer, Top-GND" (solid, pour order 36): 4547.24,3551.18 6200,3550 6200,3775 4720.47,3775.59 4547.24,3625.98
NetD2_1 on Bottom Layer "Bottom Layer, Bottom-NET00004 3" (solid, pour order 61): 900,1275 1200,1275 1375,1450 1375,2100 1500,2225 1500,2350 1575,2425 1575,2575 1650,2650 1750,2650 1800,2700 1801.18,2864.17 1958.66,3021.65 2075,3025 2075,3350 1675,3350 1100,2775 1100,2025 900,1830
NetFC1_1 on Bottom Layer "Bottom Layer, Bottom-NET00016" (solid, pour order 54): 79.72,3662.4 80,3350 280,3350 405,3475 700,3475 700,3725 148.62,3725.39
PWRGND on Bottom Layer "Bottom Layer, Bottom-PWRGND" (solid, pour order 52): 2854.33,1348.43 2897.5,1300 3021.65,1299.21 3139.76,1299.21 3175,1330 3175,1947.93 3173.53,1951.46 3126.46,1998.54 3125,2002.07 3125,2220 3120,2225 2930,2225 2925,2220 2925,1727.07 2923.53,1723.54 2893.7,1692.91 2854.33,1653.54
NetD2_1 on Bottom Layer "Bottom Layer, Bottom-NET00004 2" (solid, pour order 55): 2675,3075 2400,3350 1725,3350 1350,2975 1909.45,2972.44 1960,3021.65 2250,3025 2350,2925 2350,2675 2675,2675 2700,2700 2700,2750 2675,2775
GND on Bottom Layer "Bottom Layer, Bottom-GND" (solid, pour order 49): 6330,2457.5 6318.95,2498.75 6288.75,2528.95 6247.5,2540 5905,2540 5905,2150 5850,2150 5805,2100 5805,2025 6330,2025
NetD2_1 on Bottom Layer "Bottom Layer, Bottom-NET00004" (solid, remove dead copper, pour order 50): 2350,2175 2363.4,2125 2400,2088.4 2450,2075 2685,2075 2710,2100 2710,2150 2685,2175 2685,2695 2705,2715 2705,2726.45 2695.26,2750.67 2671.47,2761.42 2355.21,2774.78 2350,2769.78
NetC1_2 on Bottom Layer "Bottom Layer, Bottom-NET00020" (solid, pour order 51): 5805,1305 5980,1305 6030,1255 6030,1055 6205,1055 6205,1730 6280,1805 6330,1805 6330,1905 6005,1905 5955,1955 5805,1955
NetD2_1 on Bottom Layer "Bottom Layer, Bottom-NET00004 1" (solid, pour order 53): 2675,2525 2657.32,2517.68 2650,2500 2650,2350 2657.32,2332.32 2675,2325 3100,2325 3117.68,2332.32 3125,2350 3125,2500 3117.68,2517.68 3100,2525
NetD4_2 on Bottom Layer "Bottom Layer, Bottom-NET00013" (solid, pour order 56): 5205,1805 5730,1805 5730,2125 5755,2150 5755,2180 5735,2200 5565,2200 5475,2110 5205,2110
NetD6_2 on Bottom Layer "Bottom Layer, Bottom-NET00012" (solid, pour order 58): 5200,1445 5450,1445 5575,1325 5575,1025 5755,1025 5755,1085 5730,1110 5730,1720 5200,1720
NetL1_13 on Bottom Layer "Bottom Layer, Bottom-NET00002" (solid, pour order 59): 5225,3025 4725,2525 4725,2350 5475,2350 5475,2750 5750,3025 5750,3300 5225,3300
NetC2_2 on Bottom Layer "Bottom Layer, Bottom-NET00006" (solid, pour order 60): 700,3175 75,3175 75,2675 150,2675 225,2600 225,1275 700,1275
NetL1_13 on Bottom Layer "Bottom Layer, Bottom-NET00002 1" (solid, pour order 62): 4725,2525 4725,2400 4725,1000 4825,1000 5425,1000 5460.36,1014.64 5475,1050 5475,1200 5458.25,1262.5 5412.5,1308.25 5350,1325 5150,1325 5050,1425 5050,2125 5150,2225 5350,2225 5412.5,2241.75 5458.25,2287.5 5475,2350 5475,2475 5460.36,2510.36 5425,2525
NetC4_1 on Bottom Layer "Bottom Layer, Bottom-NET00038" (solid, pour order 63): 7075,50 7075,3100 6250,3100 6050,3300 5875,3300 5875,2635 6305,2635 6352.5,2622.27 6387.27,2587.5 6400,2540 6400,2025 6400,1800 6350,1750 6300,1700 6300,1350 6300,50
NetC14_1 on Bottom Layer "Bottom Layer, Bottom-NET00025" (solid, pour order 64): 3275,3100 3075,2900 3000,2900 2750,2650 2750,2600 3100,2600 3325,2825 3500,2825 3650,2975 4250,2975 4250,3375 3550,3375
NetD2_2 on Bottom Layer "Bottom Layer, Bottom-NET00003" (solid, pour order 65): 3232.32,2607.32 3225,2589.64 3225,2050 3232.32,2032.32 3250,2025 3525,2025 3542.68,2032.32 3550,2050 3550,2214.64 3557.32,2232.32 3642.68,2317.68 3660.36,2325 3914.64,2325 3932.32,2332.32 4242.68,2642.68 4250,2660.36 4250,2725 4242.68,2742.68 4225,2750 3385.36,2750 3367.68,2742.68
GND on Bottom Layer "Bottom Layer, Bottom-GND 1" (solid, pour order 57): 4547.24,3645.67 4547.24,3547.24 6075,3550 6150,3475 6150,3375 6325,3200 7075,3200 7075,3775 4645.67,3775.59

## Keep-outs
Keep-Out Layer:
  lines w10: 0,0 6259.84,0 7100,0 7100,3800 0,3800 0,0
  text ".Layer_Name" at -77.72,-1445.82 h60

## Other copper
Top Layer:
  text ".Layer_Name" at -77.72,-1445.82 h60
Bottom Layer:
  text ".Layer_Name" at -77.72,-1445.82 h60

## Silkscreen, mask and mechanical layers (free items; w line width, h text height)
Top Overlay:
  region: 1340.02,129.37 1040.02,129.37 1040.02,29.37 1340.02,29.37
  lines w5: 3000,400 3000,500 ; 1475,1400 1475,3400 2375,3400 2375,1400 1475,1400 ; 2500,1400 2500,3400 3400,3400 3400,1400 2500,1400 ; 3000,397.24 3000,497.24 4300,497.24 4300,397.24 4100,397.24 4100,197.24 3400,197.24 3400,397.24 3000,397.24 ; 5550,600 5550,2600 6450,2600 6450,600 5550,600
  text "Vin: 390 to 410" at 1669.29,3586.61 h60
  text "Iin: 2A Max" at 1708.66,3492.13 h60
  text "F1" at 173.23,3208.66 h50 r270
  text "Vout: 12Vdc nom" at 5897.64,3011.81 h60
  text "Iout: 50A max" at 5937.01,2925.2 h60
  text "EXTERNAL" at 1062.99,929.13 h60
  text "UCC27714EVM-551" at 364.17,147.64 h59.06
  text ".PRJ_Number" at 374.02,39.37 h60
  text ".PCB_Rev" at 748.03,39.37 h60
  text "SVN:" at 1366.14,39.37 h60
  text ".VersionControl_RevNumber" at 1614.17,35.43 h60
  text "-" at 975.02,28.87 h60
  text ".Layer_Name" at -77.72,-1445.82 h60
Bottom Overlay:
  text "For evaluation only; not FCC approved for resale." at 6114.17,3468.5 h60
  text "Q3" at 2342.52,2805.12 h50
  text "Q1" at 2595,2680 h50
  text "Q7" at 5745,2225 h56.88
  text "Q4" at 2332.68,2204.72 h50
  text "Q2" at 2605,2070 h50
  text "Q6" at 5728.35,893.7 h56.88
  text "For the most recent Users Guide go to WWW.TI.COM" at 1995.08,33.46 h78.74
  text ".Layer_Name" at -77.72,-1445.82 h60
Top Paste:
  text ".Layer_Name" at -77.72,-1445.82 h60
Bottom Paste:
  text ".Layer_Name" at -77.72,-1445.82 h60
Top Solder:
  text ".Layer_Name" at -77.72,-1445.82 h60
  text ".Layer_Name" at -77.72,-1445.82 h60
Bottom Solder:
  text ".Layer_Name" at -77.72,-1445.82 h60
Drill Guide:
  text ".Layer_Name" at -77.72,-1445.82 h60
M1 Board Outline:
  lines w7.87: 0,0 0,3800 7100,3800 7100,0 0,0 ; 1537.97,437.01 cw(c1537.97,486.22) 1537.97,535.43 2797.81,535.43 2935.61,673.23 cw(c2970.41,638.43) 3005.21,603.63 2838.58,437.01 1537.97,437.01
  text ".Layer_Name" at -77.72,-1445.82 h60
M2 Board Dimensions:
  rectangle: -655.22,-872.82 -530.22,-747.82
  rectangle: -530.22,-997.82 -155.22,-872.82
  lines w7: -655.22,-872.82 344.78,-872.82 ; -530.22,-997.82 -530.22,-747.82 ; -405.22,-997.82 -405.22,-747.82 ; -155.22,-997.82 -155.22,-747.82 ; 94.78,-997.82 94.78,-747.82 ; -655.22,-997.82 344.78,-997.82 344.78,-747.82 -655.22,-747.82 -655.22,-997.82
  text ".Layer_Name" at -77.72,-1445.82 h60
M3 3D STEP Top:
  text ".Layer_Name" at -77.72,-1445.82 h60
M4 3D STEP Bottom:
  text ".Layer_Name" at -77.72,-1445.82 h60
M5 Assembly Top:
  lines w7: -75.72,5683.18 1049.28,5683.18 ; -75.72,5805.68 1046.78,5805.68 ; 239.28,5563.18 239.28,5925.68 ; 624.28,5563.18 -75.72,5563.18 ; 624.28,5925.68 -75.72,5925.68 ; -75.72,5563.18 1049.28,5563.18 1049.28,5925.68 -75.72,5925.68 ; -75.72,5563.18 -75.72,5925.68
  lines w10: -946.72,-1517.49 5653.28,-1517.49 ; -946.72,-1314.16 5655.28,-1314.16 ; -946.72,-1110.82 -946.72,-1720.82 3058.28,-1720.82 5655.28,-1720.82 5655.28,-1110.82 -946.22,-1110.82 -946.22,-1720.82 629.28,-1720.82 ; 1518.28,-1720.82 1518.28,-1110.82 ; 2785.28,-1314.16 2785.28,-1110.82 ; 3625.28,-1314.16 3625.28,-1110.82 ; 4247.28,-1727.32 4247.28,-1524.49
  text "COMPONENTS MARKED 'DNP' SHOULD NOT BE POPULATED." at -141.22,6374.18 h60
  text "ASSEMBLY VARIANT:" at -141.72,6258.68 h60
  text ".VariantName" at 894.28,6258.68 h60
  text "TABLE 1" at 311.78,5960.68 h40
  text "Variant" at -50.72,5850.68 h40
  text "Label text" at 384.28,5850.68 h40
  text "001" at 16.78,5730.68 h40
  text "ChangeMe!" at 294.28,5728.18 h40
  text "002" at 16.78,5605.68 h40
  text "ChangeMe!" at 289.28,5603.18 h40
  text "PCB VIEWED FROM TOP SIDE" at -883.22,-1242.99 h60
  text "BOARD #:" at 1593.28,-1242.99 h60
  text ".PRJ_Number" at 2138.78,-1242.99 h60
  text "REV:" at 2983.28,-1242.99 h60
  text ".PCB_Rev" at 3274.78,-1242.99 h60
  text "SVN REV:" at 3821.28,-1242.99 h60
  text ".VersionControl_RevNumber" at 4327.28,-1242.99 h60
  text "IGNORE ->" at -883.22,-1445.82 h60
  text "PLOT NAME =" at -883.22,-1651.66 h60
  text ".plot_File_Name" at -77.72,-1651.66 h60
  text "GENERATED    :" at 1595.28,-1651.66 h60
  text ".Print_Date" at 2464.78,-1651.66 h60
  text ".Print_Time" at 3193.78,-1651.66 h60
  text "TEXAS INSTRUMENTS" at 4458.28,-1651.66 h60
M6 Assembly Bottom:
  lines w1: 20,95 20,20 95,20
  lines w10: -947.22,-1314.66 5654.78,-1314.66 ; -945.22,-1517.99 5654.78,-1517.99 ; 460.78,-1727.82 460.78,-1524.99 ; 1082.78,-1314.66 1082.78,-1111.32 ; 1922.78,-1314.66 1922.78,-1111.32 ; 3189.78,-1721.32 3189.78,-1111.32 ; 4078.78,-1721.32 5654.28,-1721.32 5654.28,-1111.32 -947.22,-1111.32 -947.22,-1721.32 1649.78,-1721.32 5654.78,-1721.32 5654.78,-1111.32
  text "COMPONENTS MARKED 'DNP' SHOULD NOT BE POPULATED." at 5447.28,-905.32 h60
  text ".VariantName" at 4403.28,-1021.32 h60
  text "ASSEMBLY VARIANT:" at 5442.28,-1021.32 h60
  text ".VersionControl_RevNumber" at 380.78,-1243.49 h60
  text "SVN REV:" at 886.78,-1243.49 h60
  text ".PCB_Rev" at 1433.28,-1243.49 h60
  text "REV:" at 1724.78,-1243.49 h60
  text ".PRJ_Number" at 2569.28,-1243.49 h60
  text "BOARD #:" at 3114.78,-1243.49 h60
  text "PCB VIEWED FROM BOTTOM SIDE" at 5591.28,-1243.49 h60
  text "IGNORE ->" at 1893.13,-1445.82 h60
  text "TEXAS INSTRUMENTS" at 249.78,-1652.16 h60
  text ".Print_Time" at 1514.28,-1652.16 h60
  text ".Print_Date" at 2243.28,-1652.16 h60
  text "GENERATED    :" at 3112.78,-1652.16 h60
  text ".plot_File_Name" at 4785.78,-1652.16 h60
  text "PLOT NAME =" at 5591.28,-1652.16 h60
M9 Title Sheet:
  lines w5: -100,0 25,0 ; 0,-100 0,25
  lines w10: -1146.22,454.18 -946.22,454.18 ; -1146.22,2829.18 -946.22,2829.18 ; -1146.22,5204.18 -946.22,5204.18 ; 1353.78,-1920.82 1353.78,-1720.82 ; 1353.78,7379.18 1353.78,7579.18 ; 3853.78,-1920.82 3853.78,-1720.82 ; 3853.78,7379.18 3853.78,7579.18 ; 5666.28,-1720.82 5666.28,-1110.82 10648.78,-1110.82 ; 6353.78,-1920.82 6353.78,-1720.82 ; 6353.78,7379.18 6353.78,7579.18 ; 8853.78,-1920.82 8853.78,-1720.82 ; 8853.78,7379.18 8853.78,7579.18 ; 10648.78,-1720.82 10648.78,-1110.82 ; 10648.78,-1410.82 13648.78,-1410.82 ; 10648.78,-810.82 13648.78,-810.82 ; 10649.78,-216.82 13649.78,-216.82 ; 11353.78,-1920.82 11353.78,-1720.82 ; 11353.78,7379.18 11353.78,7579.18 ; 12153.78,-1710.82 12153.78,-1110.82 ; 13648.78,-1110.82 10648.78,-1110.82 ; 13648.78,-510.82 10648.78,-510.82 ; 13653.78,-520.82 13653.78,-1720.82 ; 13653.78,283.68 10649.78,283.68 10648.78,283.68 10648.78,-216.82 10648.78,-510.82 ; 13653.78,454.18 13853.78,454.18 ; 13653.78,2829.18 13853.78,2829.18 ; 13653.78,5204.18 13853.78,5204.18 ; 10648.78,-1110.82 10648.78,-510.82 ; 13653.78,-1720.82 13653.78,7379.18 -946.22,7379.18 -946.22,-1720.82 13653.78,-1720.82 ; -1146.22,-1920.82 -1146.22,7579.18 13853.78,7579.18 13853.78,-1920.82 -1146.22,-1920.82
  text "1" at 85.11,7449.18 h70
  text "2" at 2580.78,7449.18 h70
  text "3" at 5070.12,7449.18 h70
  text "4" at 7576.79,7449.18 h70
  text "5" at 10075.78,7449.18 h70
  text "6" at 12580.78,7449.18 h70
  text "A" at -1071.22,6306.18 h70
  text "A" at 13728.78,6306.18 h70
  text "B" at -1071.22,3926.18 h70
  text "B" at 13728.78,3926.18 h70
  text "C" at -1071.22,1551.18 h70
  text "C" at 13728.78,1551.18 h70
  text "PROJECT TITLE:" at 10688.78,-309.82 h45
  text ".PRJ_Title" at 10738.78,-443.15 h70
  text "DESIGNED FOR:" at 10688.78,-610.82 h45
  text ".PRJ_Customer" at 10738.78,-750.82 h70
  text "D" at -1071.22,-818.82 h70
  text "D" at 13728.78,-818.82 h70
  text "FILE NAME:" at 10688.78,-910.82 h45
  text ".PCB_File_Name_No_Path" at 10738.78,-1030.82 h70
  text "Texas Instruments (TI) and/or its licensors do not warrant the accuracy or completeness of this specification" at 5719.28,-1192.66 h45
  text "ENGINEER:" at 10688.78,-1200.82 h45
  text "LAYOUT BY:" at 12193.78,-1200.82 h45
  text "or any information contained therein. TI and/or its licensors do not warrant that this design will meet" at 5674.29,-1305.33 h45
  text ".PRJ_Engineer" at 10738.78,-1355.82 h70
  text ".PCB_Layout" at 12244.28,-1355.82 h70
  text "the specifications, will be suitable for your application or fit for any particular purpose, or will operate in" at 5674.29,-1417.99 h45
  text ".Layer_Name" at -77.72,-1445.82 h60
  text "ALTIUM DESIGNER VERSION:" at 12193.78,-1510.82 h45
  text "an implementation. TI and/or its licensors do not warrant that the design is production worthy. You should" at 5674.29,-1530.66 h45
  text "completely validate and test your design implementation to confirm the system functionality for your application." at 5719.28,-1643.32 h45
  text ".print_Scale" at 10738.78,-1644.15 h70
  text ".Application_BuildNumber" at 12244.28,-1644.15 h70
  text "1" at 85.11,-1850.82 h70
  text "2" at 2580.78,-1850.82 h70
  text "3" at 5070.12,-1850.82 h70
  text "4" at 7576.79,-1850.82 h70
  text "5" at 10075.78,-1850.82 h70
  text "6" at 12580.78,-1850.82 h70
M10 Fab Notes:
  drawing of 207 lines, arcs and shapes, not listed
  text "DESIGN INFORMATION" at 11726.29,6222.68 h60
  text "(REFER ALSO ARRAY/PANEL PROFILING INFORMATION)" at 11364.74,6060.96 h60
  text "BOARD SIZE" at 10678.74,6056.68 h60
  text "180.34mm" at 11141.06,5928.85 h60
  text "X" at 11646.74,5928.85 h60
  text "96.52mm" at 11878.06,5928.85 h60
  text "Number of Layers :" at 11081.73,5731.68 h60
  text "2" at 12176.55,5721.68 h60
  text "MIN. TRACK WIDTH:" at 11081.73,5592.68 h60
  text "12" at 12177.98,5592.68 h60
  text "MIL" at 12332.73,5592.68 h60
  text "MIN. CLEARANCE:" at 11081.73,5460.68 h60
  text "12" at 12177.98,5460.68 h60
  text "MIL" at 12332.73,5460.68 h60
  text "MIN. VIA PAD SIZE:" at 11081.73,5328.68 h60
  text "24" at 12147.99,5328.68 h60
  text "MIL" at 12332.73,5328.68 h60
  text "0.05mm (2MIL)" at 11776.74,5186.97 h60
  text "MINIMUM ANNULAR RING" at 10752.5,5182.68 h60
  text "EXTERNAL" at 12484.74,5182.68 h60
  text "PER" at 10952.5,5064.68 h60
  text "IPC-D-275 CLASS 2 LEVEL C" at 11172.5,5064.68 h60
  text "MIL, HOLES" at 12660.73,4952.39 h60
  text "+/-" at 12268.28,4951.68 h60
  text "+/-" at 13122.28,4951.68 h60
  text "REGISTRATION TOLERANCES:" at 10752.5,4946.68 h60
  text "METAL" at 11952.28,4946.68 h60
  text "5" at 12528.48,4946.68 h60
  text "3" at 13361.48,4946.68 h60
  text "MIL" at 13477.73,4946.68 h60
  text "MATERIAL:" at 10677.74,4737.22 h60
  text "FR-4 High Tg" at 11664.18,4596.88 h60
  text "X" at 11507.87,4590.55 h60
  text "FR-4" at 11138.74,4588.32 h60
  text "OTHER" at 12586.74,4588.32 h60
  text "62 MIL (1.6mm) +/-10%" at 11418.84,4425.6 h60
  text "THICKNESS:" at 10752.5,4421.32 h60
  text "X" at 11290.67,4421.32 h60
  text "OTHER" at 12703.74,4421.32 h60
  text "TOLERANCE:" at 10752.5,4263.32 h60
  text "X" at 11591.81,4263.32 h60
  text "ANSI IPC-6012 TYPE 3 CLASS 2" at 11778.75,4263.32 h60
  text "OTHER +/-" at 11778.74,4107.32 h60
  text "BOW & TWIST:" at 10752.5,3950.32 h60
  text "X" at 11591.81,3950.32 h60
  text "ANSI IPC-6012 TYPE 3 CLASS 2" at 11778.75,3950.32 h60
  text "OTHER +/-" at 11778.74,3791.81 h60
  text "COPPER THICKNESS (FINISHED):" at 10677.74,3656.32 h60
  text "X" at 12940,3510 h60
  text "1.4MIL (1oz)" at 11557.73,3503.6 h60
  text "2MIL (1.4oz)" at 12324.74,3503.6 h60
  text "4oz" at 13051.74,3503.6 h60
  text "OUTER:" at 11034.74,3499.32 h60
  text "1.4MIL (1oz)" at 11557.73,3346.6 h60
  text "2.8MIL (2oz)" at 12324.74,3346.6 h60
  text "N/A" at 13051.28,3346.96 h60
  text "INNER SIGNAL:" at 10745.65,3342.32 h60
  text "DRILLING:" at 10677.74,3203.32 h60
  text "REFERENCE:" at 10752.5,3086.32 h60
  text "X" at 11400.74,3086.32 h60
  text "AS SHOWN" at 11587.73,3086.32 h60
  text "X" at 12301.74,3086.32 h60
  text "NC_DRILL FILES" at 12438.73,3086.32 h60
  text "X" at 12630,2940 h60
  text "PTH MIN COPPER THICKNESS:" at 10752.5,2928.32 h60
  text "1MIL" at 12239.73,2928.32 h60
  text "1oz" at 12736.74,2928.32 h60
  text "BOARD FINISH:" at 10677.74,2769.32 h60
  text "SILKSCREEN:" at 10832.96,2651.32 h60
  text "X" at 11781.74,2651.32 h60
  text "TOP" at 11907.73,2651.32 h60
  text "X" at 12291.74,2651.32 h60
  text "BOTTOM" at 12418.73,2651.32 h60
  text "SILKSCREEN COLOR:" at 10832.96,2484.32 h60
  text "X" at 11780.69,2484.32 h60
  text "WHITE" at 11907.73,2484.32 h60
  text "OTHER" at 12418.73,2484.32 h60
  text "SOLDER RESIST COLOR:" at 10832.96,2314.32 h60
  text "X" at 11400.7,2155.12 h60
  text "GREEN" at 11527.73,2155.12 h60
  text "BLUE" at 12118.73,2155.12 h60
  text "OTHER" at 12656.74,2155.12 h60
  text "IMMERSION GOLD (ENIG)" at 11738.73,1966.6 h60
  text "SURFACE FINISH:" at 10677.74,1962.32 h60
  text "X" at 11543.31,1956.69 h60
  text "IMM. TIN/SILVER OR EQUIV" at 11007.28,1805.32 h60
  text "OTHER" at 12438.74,1805.32 h60
  text "ARRAY/PANEL:" at 10677.74,1626.32 h60
  text "CUT AND TRIM PER MECH LAYER 1" at 11738.74,1622.03 h60
  text "X" at 12411.46,1476.6 h60
  text "N.C. ROUTE" at 11738.73,1470.32 h60
  text "V. SCORE" at 12604.74,1470.32 h60
  text "CERTIFICATION:" at 10677.74,1333.32 h60
  text "MATERIALS AND WORKMANSHIP FOR ALL PCBS" at 11402.74,1333.32 h60
  text "TO MEET OR EXCEED THE REQUIREMENTS OF:" at 11402.74,1235.32 h60
  text "X" at 11029.24,1098.81 h60
  text "ANSI IPC-A-600F CLASS ->" at 11168.24,1098.81 h60
  text "X" at 12807.29,1098.81 h60
  text "2" at 12926.24,1098.81 h60
  text "1" at 12611.24,1097.32 h60
  text "3" at 13280.24,1097.32 h60
  text "X" at 11031.29,939.32 h60
  text "UL 94V-0" at 11168.24,939.32 h60
  text "X" at 11843.29,939.32 h60
  text "RoHS" at 11980.24,939.32 h60
  text "OTHER" at 12624.64,939.32 h60
  text "PER ORDER" at 13021.7,939.32 h60
  text "ADDITIONAL REQUIREMENTS:" at 10677.74,798.32 h60
  text "MICROSECTION:" at 10752.5,683.32 h60
  text "YES" at 11658.24,683.32 h60
  text "X" at 12405.51,539.37 h60
  text "REQUIRED" at 12519.73,527.17 h60
  text "BARE BOARD ELEC. TEST:" at 10752.5,524.32 h60
  text "NONE" at 12058.24,524.32 h60
  text "PER ORDER" at 13111.74,524.32 h60
  text "X" at 13080,370 h60
  text "MANUFACTURER'S ID/LOGO:" at 10752.5,367.32 h60
  text "RAIL" at 12218.24,363.03 h60
  text "METAL" at 12710.05,363.03 h60
  text "SILK" at 13221.73,363.03 h60
  text ".Layer_Name" at -77.72,-1445.82 h60
M11 Gerber Information:
  lines w10: -946.72,-1517.49 5653.28,-1517.49 ; -946.72,-1314.16 5655.28,-1314.16 ; -946.72,-1110.82 -946.72,-1720.82 3058.28,-1720.82 5655.28,-1720.82 5655.28,-1110.82 -946.22,-1110.82 -946.22,-1720.82 629.28,-1720.82 ; 1518.28,-1720.82 1518.28,-1110.82 ; 2785.28,-1314.16 2785.28,-1110.82 ; 3625.28,-1314.16 3625.28,-1110.82 ; 4247.28,-1727.32 4247.28,-1524.49
  text "ALL ARTWORK VIEWED FROM TOP SIDE" at -883.22,-1242.99 h60
  text "BOARD #:" at 1593.28,-1242.99 h60
  text ".PRJ_Number" at 2138.78,-1242.99 h60
  text "REV:" at 2983.28,-1242.99 h60
  text ".PCB_Rev" at 3274.78,-1242.99 h60
  text "SVN REV:" at 3821.28,-1242.99 h60
  text ".VersionControl_RevNumber" at 4327.28,-1242.99 h60
  text "LAYER NAME =" at -883.22,-1445.82 h60
  text "PLOT NAME =" at -883.22,-1651.66 h60
  text ".plot_File_Name" at -77.72,-1651.66 h60
  text "GENERATED    :" at 1595.28,-1651.66 h60
  text ".Print_Date" at 2464.78,-1651.66 h60
  text ".Print_Time" at 3193.78,-1651.66 h60
  text "TEXAS INSTRUMENTS" at 4458.28,-1651.66 h60
M12 Stackup:
  lines w6: 10705.28,6872.68 13255.28,6872.68 ; 10705.28,6977.08 13255.28,6977.08 ; 10645.28,6387.68 ccw(c10679.28,6387.68) 10679.28,6353.68 13281.28,6353.68 ccw(c13281.28,6387.68) 13315.28,6387.68 13315.28,7093.68 ccw(c13281.28,7093.68) 13281.28,7127.68 10679.28,7127.68 ccw(c10679.28,7093.68) 10645.28,7093.68 10645.28,6387.68
  text "The Stackup Legend below this is static." at 10950.78,7287.18 h60
  text "If you change the stackup, update the Legend." at 10960.78,7197.18 h60
  text "Layer Stack Up Detail for: Ref_Design.PcbDoc" at 10705.28,7009.78 h57
  text "Layer" at 10705.28,6938.08 h24
  text "Gerber" at 11601.09,6938.08 h24
  text "Copper" at 12164.61,6938.08 h24
  text "Dielectric" at 12767.32,6938.08 h24
  text "Name" at 10705.28,6890.08 h24
  text "Document" at 11601.09,6890.08 h24
  text "Thickness" at 12164.61,6890.08 h24
  text "Material" at 12767.32,6890.08 h24
  text "Top Solder Mask" at 10705.28,6797.11 h34
  text "(.GTS)" at 11601.09,6797.11 h34
  text "Solder Resist" at 12767.32,6797.11 h34
  text "Top Layer" at 10705.28,6700.36 h34
  text "(.GTL)" at 11601.09,6700.36 h34
  text "5.6mil" at 12164.61,6700.36 h34
  text "FR-4" at 12767.32,6651.99 h34
  text "Bottom Layer" at 10705.28,6603.61 h34
  text "(.GBL)" at 11601.09,6603.61 h34
  text "5.6mil" at 12164.61,6603.61 h34
  text "Bottom Solder Mask" at 10705.28,6506.86 h34
  text "(.GBS)" at 11601.09,6506.86 h34
  text "Solder Resist" at 12767.32,6506.86 h34
  text ".Layer_Name" at -77.72,-1445.82 h60
M13 Component Bodies Top:
  text ".Layer_Name" at -77.72,-1445.82 h60
M14 Component Bodies Bottom:
  text ".Layer_Name" at -77.72,-1445.82 h60
M15 Courtyards Top:
  text ".Layer_Name" at -77.72,-1445.82 h60
M16 Courtyards Bottom:
  text ".Layer_Name" at -77.72,-1445.82 h60
Drill Drawing:
  text ".legend" at 3026.36,4129.44 h60
  text "Drill Table" at 3051.36,3944.44 h60
  text ".Layer_Name" at -77.72,-1445.82 h60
